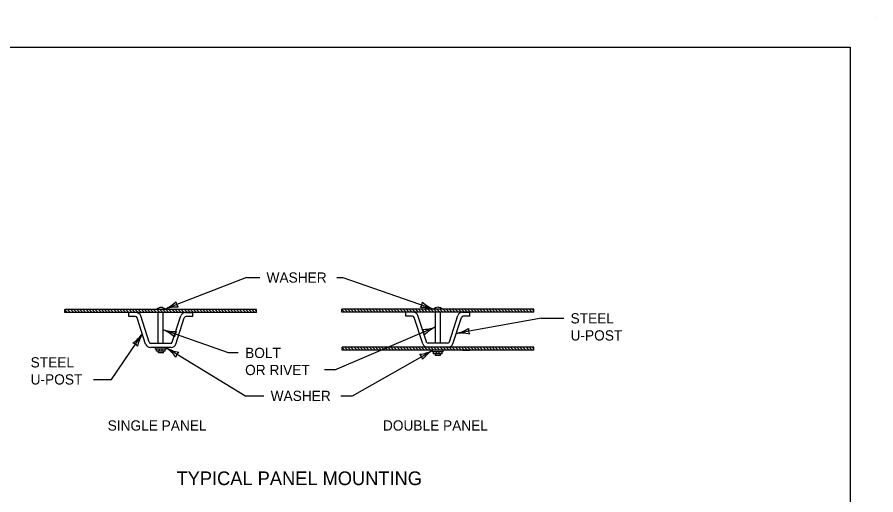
# Model space of a CAD drawing. Extents: x 49991.4 to 50021, y 49987.6 to 50011.4.
# Drawn here: x 50011.87 to 50016.9, y 49996.38 to 49999.18 of the extents above; entities that cross this region are included whole.
import ezdxf

# ---------------------------------------------------------------- set-up
doc = ezdxf.new("R2010")
doc.units = 0
for name, color, linetype in [('Level 1', 7, 'Continuous'), ('Level 2', 7, 'Continuous'), ('Level 3', 7, 'Continuous')]:
    doc.layers.add(name, color=color, linetype=linetype)

msp = doc.modelspace()

# ---------------------------------------------------------------- linework, layer by layer
at = {"layer": 'Level 1'}
for p, q in [((50016.9001, 49999.1756), (50016.9001, 49999.1756)), ((50012.1473, 49997.4466), (50012.1473, 49997.4642)), ((50013.2714, 49997.4642), (50012.1473, 49997.4642)), ((50012.1634, 49997.4466), (50012.1473, 49997.4626)), ((50012.1814, 49997.4466), (50012.1637, 49997.4642)), ((50012.1994, 49997.4466), (50012.1817, 49997.4642)), ((50012.2174, 49997.4466), (50012.1997, 49997.4642)), ((50012.2354, 49997.4466), (50012.2177, 49997.4642)), ((50012.2534, 49997.4466), (50012.2357, 49997.4642)), ((50012.2714, 49997.4466), (50012.2537, 49997.4642)), ((50012.2894, 49997.4466), (50012.2717, 49997.4642)), ((50012.3074, 49997.4466), (50012.2897, 49997.4642)), ((50012.3254, 49997.4466), (50012.3077, 49997.4642)), ((50012.3434, 49997.4466), (50012.3257, 49997.4642)), ((50012.3614, 49997.4466), (50012.3437, 49997.4642)), ((50012.3794, 49997.4466), (50012.3617, 49997.4642)), ((50012.3974, 49997.4466), (50012.3797, 49997.4642)), ((50012.4154, 49997.4466), (50012.3977, 49997.4642)), ((50012.4334, 49997.4466), (50012.4157, 49997.4642)), ((50012.4514, 49997.4466), (50012.4337, 49997.4642)), ((50012.4694, 49997.4466), (50012.4517, 49997.4642)), ((50012.4874, 49997.4466), (50012.4697, 49997.4642)), ((50012.5054, 49997.4466), (50012.4877, 49997.4642)), ((50012.5234, 49997.4466), (50012.5057, 49997.4642)), ((50012.5414, 49997.4466), (50012.5237, 49997.4642)), ((50012.5594, 49997.4466), (50012.5417, 49997.4642)), ((50012.5774, 49997.4466), (50012.5597, 49997.4642)), ((50012.5954, 49997.4466), (50012.5777, 49997.4642)), ((50012.6134, 49997.4466), (50012.5957, 49997.4642)), ((50012.6314, 49997.4466), (50012.6137, 49997.4642)), ((50012.6494, 49997.4466), (50012.6317, 49997.4642)), ((50012.6674, 49997.4466), (50012.6497, 49997.4642)), ((50012.6854, 49997.4466), (50012.6677, 49997.4642)), ((50012.7034, 49997.4466), (50012.6857, 49997.4642)), ((50012.7214, 49997.4466), (50012.7037, 49997.4642)), ((50012.7394, 49997.4466), (50012.7217, 49997.4642)), ((50012.7574, 49997.4466), (50012.7397, 49997.4642)), ((50012.7754, 49997.4466), (50012.7577, 49997.4642)), ((50012.7934, 49997.4466), (50012.7757, 49997.4642)), ((50012.8114, 49997.4466), (50012.7937, 49997.4642)), ((50012.8294, 49997.4466), (50012.8117, 49997.4642)), ((50012.8474, 49997.4466), (50012.8297, 49997.4642)), ((50012.8654, 49997.4466), (50012.8477, 49997.4642)), ((50012.8834, 49997.4466), (50012.8657, 49997.4642)), ((50012.9014, 49997.4466), (50012.8837, 49997.4642)), ((50012.9194, 49997.4466), (50012.9017, 49997.4642)), ((50012.9374, 49997.4466), (50012.9197, 49997.4642)), ((50012.9554, 49997.4466), (50012.9377, 49997.4642)), ((50012.9734, 49997.4466), (50012.9557, 49997.4642)), ((50012.9914, 49997.4466), (50012.9737, 49997.4642)), ((50013.0094, 49997.4466), (50012.9917, 49997.4642)), ((50013.0274, 49997.4466), (50013.0097, 49997.4642)), ((50013.0454, 49997.4466), (50013.0277, 49997.4642)), ((50013.0634, 49997.4466), (50013.0457, 49997.4642)), ((50013.0814, 49997.4466), (50013.0637, 49997.4642)), ((50013.0994, 49997.4466), (50013.0817, 49997.4642)), ((50013.1174, 49997.4466), (50013.0997, 49997.4642)), ((50013.1354, 49997.4466), (50013.1177, 49997.4642)), ((50013.1534, 49997.4466), (50013.1357, 49997.4642)), ((50013.1714, 49997.4466), (50013.1537, 49997.4642)), ((50013.1894, 49997.4466), (50013.1717, 49997.4642)), ((50013.2074, 49997.4466), (50013.1897, 49997.4642)), ((50013.2254, 49997.4466), (50013.2077, 49997.4642)), ((50013.2434, 49997.4466), (50013.2257, 49997.4642)), ((50013.2614, 49997.4466), (50013.2437, 49997.4642)), ((50013.2714, 49997.4546), (50013.2617, 49997.4642)), ((50013.2714, 49997.4466), (50013.2714, 49997.4642)), ((50013.7714, 49997.4482), (50013.7714, 49997.4658)), ((50014.8955, 49997.4658), (50013.7714, 49997.4658)), ((50013.7875, 49997.4482), (50013.7714, 49997.4642)), ((50014.8955, 49997.4482), (50013.7714, 49997.4482)), ((50013.8055, 49997.4482), (50013.7878, 49997.4658)), ((50013.8235, 49997.4482), (50013.8058, 49997.4658)), ((50013.8415, 49997.4482), (50013.8238, 49997.4658)), ((50013.8595, 49997.4482), (50013.8418, 49997.4658)), ((50013.8775, 49997.4482), (50013.8598, 49997.4658)), ((50013.8955, 49997.4482), (50013.8778, 49997.4658)), ((50013.9135, 49997.4482), (50013.8958, 49997.4658)), ((50013.9315, 49997.4482), (50013.9138, 49997.4658)), ((50013.9495, 49997.4482), (50013.9318, 49997.4658)), ((50013.9675, 49997.4482), (50013.9498, 49997.4658)), ((50013.9855, 49997.4482), (50013.9678, 49997.4658)), ((50014.0035, 49997.4482), (50013.9858, 49997.4658)), ((50014.0215, 49997.4482), (50014.0038, 49997.4658)), ((50014.0395, 49997.4482), (50014.0218, 49997.4658)), ((50014.0575, 49997.4482), (50014.0398, 49997.4658)), ((50014.0755, 49997.4482), (50014.0578, 49997.4658)), ((50014.0935, 49997.4482), (50014.0758, 49997.4658)), ((50014.1115, 49997.4482), (50014.0938, 49997.4658)), ((50014.1295, 49997.4482), (50014.1118, 49997.4658)), ((50014.1475, 49997.4482), (50014.1298, 49997.4658)), ((50014.1459, 49997.4247), (50014.1459, 49997.4482)), ((50014.1886, 49997.4482), (50014.1459, 49997.4482)), ((50014.1655, 49997.4482), (50014.1478, 49997.4658)), ((50014.1835, 49997.4482), (50014.1658, 49997.4658)), ((50014.2015, 49997.4482), (50014.1838, 49997.4658)), ((50014.2195, 49997.4482), (50014.2018, 49997.4658)), ((50014.2375, 49997.4482), (50014.2198, 49997.4658)), ((50014.2555, 49997.4482), (50014.2378, 49997.4658)), ((50014.2735, 49997.4482), (50014.2558, 49997.4658)), ((50014.2915, 49997.4482), (50014.2738, 49997.4658)), ((50014.3095, 49997.4482), (50014.2918, 49997.4658)), ((50014.3275, 49997.4482), (50014.3098, 49997.4658)), ((50014.3189, 49997.2665), (50014.3189, 49997.4482)), ((50014.3455, 49997.4482), (50014.3278, 49997.4658)), ((50014.3635, 49997.4482), (50014.3458, 49997.4658)), ((50014.3481, 49997.2665), (50014.3481, 49997.4482)), ((50014.3815, 49997.4482), (50014.3638, 49997.4658)), ((50014.3995, 49997.4482), (50014.3818, 49997.4658)), ((50014.4175, 49997.4482), (50014.3998, 49997.4658)), ((50014.4355, 49997.4482), (50014.4178, 49997.4658)), ((50014.4535, 49997.4482), (50014.4358, 49997.4658)), ((50014.4715, 49997.4482), (50014.4538, 49997.4658)), ((50014.4895, 49997.4482), (50014.4718, 49997.4658)), ((50014.4783, 49997.4482), (50014.521, 49997.4482)), ((50014.5075, 49997.4482), (50014.4898, 49997.4658)), ((50014.5255, 49997.4482), (50014.5078, 49997.4658)), ((50014.521, 49997.4247), (50014.521, 49997.4482)), ((50014.5435, 49997.4482), (50014.5258, 49997.4658)), ((50014.5615, 49997.4482), (50014.5438, 49997.4658)), ((50014.5795, 49997.4482), (50014.5618, 49997.4658)), ((50014.5975, 49997.4482), (50014.5798, 49997.4658)), ((50014.6155, 49997.4482), (50014.5978, 49997.4658)), ((50014.6335, 49997.4482), (50014.6158, 49997.4658)), ((50014.6515, 49997.4482), (50014.6338, 49997.4658)), ((50014.6695, 49997.4482), (50014.6518, 49997.4658)), ((50014.6875, 49997.4482), (50014.6698, 49997.4658)), ((50014.7055, 49997.4482), (50014.6878, 49997.4658)), ((50014.7235, 49997.4482), (50014.7058, 49997.4658)), ((50014.7415, 49997.4482), (50014.7238, 49997.4658)), ((50014.7595, 49997.4482), (50014.7418, 49997.4658)), ((50014.7775, 49997.4482), (50014.7598, 49997.4658)), ((50014.7955, 49997.4482), (50014.7778, 49997.4658)), ((50014.8135, 49997.4482), (50014.7958, 49997.4658)), ((50014.8315, 49997.4482), (50014.8138, 49997.4658)), ((50014.8495, 49997.4482), (50014.8318, 49997.4658)), ((50014.8675, 49997.4482), (50014.8498, 49997.4658)), ((50014.8855, 49997.4482), (50014.8678, 49997.4658)), ((50014.8955, 49997.4562), (50014.8858, 49997.4658)), ((50014.8955, 49997.4482), (50014.8955, 49997.4658)), ((50013.2714, 49997.4466), (50012.1473, 49997.4466)), ((50012.5218, 49997.4231), (50012.5218, 49997.4466)), ((50012.5645, 49997.4466), (50012.5218, 49997.4466)), ((50012.5601, 49997.4231), (50012.5218, 49997.4231)), ((50012.6208, 49997.2617), (50012.5713, 49997.415)), ((50012.6418, 49997.2731), (50012.5923, 49997.4263)), ((50012.6948, 49997.2649), (50012.6948, 49997.4466)), ((50012.724, 49997.2649), (50012.724, 49997.4466)), ((50012.7769, 49997.273), (50012.8263, 49997.4263)), ((50012.7979, 49997.2617), (50012.8474, 49997.415)), ((50012.8542, 49997.4466), (50012.8969, 49997.4466)), ((50012.8969, 49997.4231), (50012.8585, 49997.4231)), ((50012.8969, 49997.4231), (50012.8969, 49997.4466)), ((50014.1842, 49997.4247), (50014.1459, 49997.4247)), ((50014.2449, 49997.2633), (50014.1954, 49997.4166)), ((50014.2659, 49997.2747), (50014.2164, 49997.4279)), ((50014.401, 49997.2746), (50014.4504, 49997.4279)), ((50014.422, 49997.2633), (50014.4715, 49997.4166)), ((50014.521, 49997.4247), (50014.4826, 49997.4247)), ((50012.7657, 49997.2649), (50012.6529, 49997.2649)), ((50014.3898, 49997.2665), (50014.277, 49997.2665)), ((50012.7701, 49997.2414), (50012.6486, 49997.2414)), ((50012.6787, 49997.2311), (50012.6787, 49997.2414)), ((50012.7413, 49997.2311), (50012.6787, 49997.2311)), ((50012.6846, 49997.2201), (50012.6846, 49997.2311)), ((50012.7354, 49997.2201), (50012.6846, 49997.2201)), ((50012.6955, 49997.2099), (50012.6955, 49997.2201)), ((50012.7247, 49997.2099), (50012.6955, 49997.2099)), ((50012.7015, 49997.2201), (50012.7015, 49997.2311)), ((50012.7186, 49997.2201), (50012.7186, 49997.2311)), ((50012.7247, 49997.2099), (50012.7247, 49997.2201)), ((50012.7354, 49997.2201), (50012.7354, 49997.2311)), ((50012.7413, 49997.2311), (50012.7413, 49997.2414)), ((50013.7717, 49997.2253), (50013.7717, 49997.2429)), ((50014.8958, 49997.2429), (50013.7717, 49997.2429)), ((50013.7878, 49997.2253), (50013.7717, 49997.2413)), ((50014.8958, 49997.2253), (50013.7717, 49997.2253)), ((50013.8058, 49997.2253), (50013.7881, 49997.2429)), ((50013.8238, 49997.2253), (50013.8061, 49997.2429)), ((50013.8418, 49997.2253), (50013.8241, 49997.2429)), ((50013.8598, 49997.2253), (50013.8421, 49997.2429)), ((50013.8778, 49997.2253), (50013.8601, 49997.2429)), ((50013.8958, 49997.2253), (50013.8781, 49997.2429)), ((50013.9138, 49997.2253), (50013.8961, 49997.2429)), ((50013.9318, 49997.2253), (50013.9141, 49997.2429)), ((50013.9498, 49997.2253), (50013.9321, 49997.2429)), ((50013.9678, 49997.2253), (50013.9501, 49997.2429)), ((50013.9858, 49997.2253), (50013.9681, 49997.2429)), ((50014.0038, 49997.2253), (50013.9861, 49997.2429)), ((50014.0218, 49997.2253), (50014.0041, 49997.2429)), ((50014.0398, 49997.2253), (50014.0221, 49997.2429)), ((50014.0578, 49997.2253), (50014.0401, 49997.2429)), ((50014.0758, 49997.2253), (50014.0581, 49997.2429)), ((50014.0938, 49997.2253), (50014.0761, 49997.2429)), ((50014.1118, 49997.2253), (50014.0941, 49997.2429)), ((50014.1298, 49997.2253), (50014.1121, 49997.2429)), ((50014.1478, 49997.2253), (50014.1301, 49997.2429)), ((50014.1889, 49997.2253), (50014.1462, 49997.2253)), ((50014.1658, 49997.2253), (50014.1481, 49997.2429)), ((50014.1838, 49997.2253), (50014.1661, 49997.2429)), ((50014.2018, 49997.2253), (50014.1841, 49997.2429)), ((50014.2198, 49997.2253), (50014.2021, 49997.2429)), ((50014.2378, 49997.2253), (50014.2201, 49997.2429)), ((50014.2558, 49997.2253), (50014.2381, 49997.2429)), ((50014.2738, 49997.2253), (50014.2561, 49997.2429)), ((50014.3942, 49997.243), (50014.2727, 49997.243)), ((50014.2918, 49997.2253), (50014.2741, 49997.2429)), ((50014.3098, 49997.2253), (50014.2921, 49997.2429)), ((50014.3021, 49997.2153), (50014.3021, 49997.2253)), ((50014.3647, 49997.2153), (50014.3021, 49997.2153)), ((50014.308, 49997.2043), (50014.308, 49997.2153)), ((50014.3588, 49997.2043), (50014.308, 49997.2043)), ((50014.3278, 49997.2253), (50014.3101, 49997.2429)), ((50014.3189, 49997.1941), (50014.3189, 49997.2043)), ((50014.3249, 49997.2043), (50014.3249, 49997.2153)), ((50014.3458, 49997.2253), (50014.3281, 49997.2429)), ((50014.342, 49997.2043), (50014.342, 49997.2153)), ((50014.3638, 49997.2253), (50014.3461, 49997.2429)), ((50014.3481, 49997.1941), (50014.3481, 49997.2043)), ((50014.3588, 49997.2043), (50014.3588, 49997.2153)), ((50014.3818, 49997.2253), (50014.3641, 49997.2429)), ((50014.3647, 49997.2153), (50014.3647, 49997.2253)), ((50014.3998, 49997.2253), (50014.3821, 49997.2429)), ((50014.4178, 49997.2253), (50014.4001, 49997.2429)), ((50014.4358, 49997.2253), (50014.4181, 49997.2429)), ((50014.4538, 49997.2253), (50014.4361, 49997.2429)), ((50014.4718, 49997.2253), (50014.4541, 49997.2429)), ((50014.4898, 49997.2253), (50014.4721, 49997.2429)), ((50014.4786, 49997.2253), (50014.5213, 49997.2253)), ((50014.5078, 49997.2253), (50014.4901, 49997.2429)), ((50014.5258, 49997.2253), (50014.5081, 49997.2429)), ((50014.5438, 49997.2253), (50014.5261, 49997.2429)), ((50014.5618, 49997.2253), (50014.5441, 49997.2429)), ((50014.5798, 49997.2253), (50014.5621, 49997.2429)), ((50014.5978, 49997.2253), (50014.5801, 49997.2429)), ((50014.6158, 49997.2253), (50014.5981, 49997.2429)), ((50014.6338, 49997.2253), (50014.6161, 49997.2429)), ((50014.6518, 49997.2253), (50014.6341, 49997.2429)), ((50014.6698, 49997.2253), (50014.6521, 49997.2429)), ((50014.6878, 49997.2253), (50014.6701, 49997.2429)), ((50014.7058, 49997.2253), (50014.6881, 49997.2429)), ((50014.7238, 49997.2253), (50014.7061, 49997.2429)), ((50014.7418, 49997.2253), (50014.7241, 49997.2429)), ((50014.7598, 49997.2253), (50014.7421, 49997.2429)), ((50014.7778, 49997.2253), (50014.7601, 49997.2429)), ((50014.7958, 49997.2253), (50014.7781, 49997.2429)), ((50014.8138, 49997.2253), (50014.7961, 49997.2429)), ((50014.8318, 49997.2253), (50014.8141, 49997.2429)), ((50014.8498, 49997.2253), (50014.8321, 49997.2429)), ((50014.8678, 49997.2253), (50014.8501, 49997.2429)), ((50014.8858, 49997.2253), (50014.8681, 49997.2429)), ((50014.8958, 49997.2333), (50014.8861, 49997.2429)), ((50014.8958, 49997.2253), (50014.8958, 49997.2429)), ((50014.3481, 49997.1941), (50014.3189, 49997.1941))]:
    msp.add_line(p, q, dxfattribs=at)
msp.add_lwpolyline([(49999.3835, 49998.9992), (50016.7501, 49998.9992), (50016.7501, 49987.7988), (49999.3835, 49987.7988)], close=True, dxfattribs=at)
for centre, radius, start, end in [((50012.7104, 49997.4409), 0.0347, 42.1586, 137.8397), ((50014.1887, 49997.4189), 0.0293, 17.888, 90), ((50014.3345, 49997.4425), 0.0347, 42.1586, 137.8397), ((50014.4783, 49997.4189), 0.0293, 90, 162.1111), ((50012.5602, 49997.4113), 0.0117, 17.8891, 90), ((50012.5646, 49997.4173), 0.0293, 17.888, 90), ((50012.8542, 49997.4173), 0.0293, 90, 162.1111), ((50012.8585, 49997.4113), 0.0117, 90, 162.1109), ((50014.1843, 49997.4129), 0.0117, 17.8891, 90), ((50014.4826, 49997.4129), 0.0117, 90, 162.1109), ((50012.6487, 49997.2707), 0.0293, 197.8891, 270), ((50012.6529, 49997.2767), 0.0117, 197.8889, 270), ((50012.7657, 49997.2767), 0.0117, 270, 342.1111), ((50012.7701, 49997.2707), 0.0293, 270, 342.1109), ((50014.2728, 49997.2723), 0.0293, 197.8891, 270), ((50014.277, 49997.2783), 0.0117, 197.8889, 270), ((50014.3898, 49997.2783), 0.0117, 270, 342.1111), ((50014.3942, 49997.2723), 0.0293, 270, 342.1109)]:
    msp.add_arc(centre, radius, start, end, dxfattribs=at)
at = {"layer": 'Level 3'}
for p, q in [((50013.2117, 49997.6512), (50012.7338, 49997.4666)), ((50013.2117, 49997.6512), (50013.2895, 49997.6512)), ((50013.7409, 49997.6512), (50013.776, 49997.6512)), ((50013.776, 49997.6512), (50014.3089, 49997.4659)), ((50014.941, 49997.4123), (50014.4414, 49997.3232)), ((50014.941, 49997.4123), (50015.0712, 49997.4123)), ((50013.7293, 49997.1098), (50014.3189, 49997.3616)), ((50012.4205, 49997.0546), (50012.6017, 49997.3209)), ((50013.1067, 49997.2098), (50012.724, 49997.3447)), ((50013.202, 49996.9583), (50012.7413, 49997.2393)), ((50013.1639, 49997.2098), (50013.1067, 49997.2098)), ((50013.8325, 49996.9583), (50014.3021, 49997.2246)), ((50013.7293, 49997.1098), (50013.669, 49997.1098)), ((50012.3148, 49997.0546), (50012.4205, 49997.0546)), ((50013.202, 49996.9583), (50013.3134, 49996.9583)), ((50013.7648, 49996.9583), (50013.8325, 49996.9583))]:
    msp.add_line(p, q, dxfattribs=at)
for centre, radius, start, end in [((50012.6392, 49997.6795), 0.233, 293.9466, 313.1964), ((50012.8534, 49997.5128), 0.0548, 183.2581, 218.9804), ((50014.1878, 49997.508), 0.0548, 322.9653, 358.6877), ((50014.3905, 49997.6727), 0.2223, 228.2825, 248.466), ((50012.8053, 49997.2561), 0.2223, 88.5753, 108.7588), ((50014.2433, 49997.2423), 0.233, 73.6538, 92.9036), ((50014.2401, 49997.5695), 0.2223, 270.5813, 290.7648), ((50014.201, 49997.3113), 0.0548, 5.2641, 40.9864), ((50014.4209, 49997.1521), 0.233, 115.9526, 135.2024), ((50014.3879, 49997.55), 0.233, 283.2775, 302.5273), ((50014.5675, 49997.3465), 0.0548, 172.589, 208.3113), ((50012.4232, 49997.4534), 0.2223, 303.2183, 323.4019), ((50012.8006, 49997.1994), 0.233, 148.5896, 167.8395), ((50012.6416, 49997.1382), 0.2223, 48.0448, 68.2283), ((50012.7905, 49997.568), 0.233, 253.4161, 272.6659), ((50012.845, 49997.3021), 0.0548, 142.7276, 178.4499), ((50014.4727, 49997.1031), 0.2223, 77.9062, 98.0897), ((50012.5296, 49997.2149), 0.0548, 37.9012, 73.6235), ((50012.6178, 49997.0545), 0.2223, 36.0723, 56.2558), ((50012.8527, 49997.444), 0.233, 241.4436, 260.6934), ((50012.8508, 49997.1726), 0.0548, 130.7551, 166.4774), ((50014.2005, 49997.4224), 0.2223, 277.0137, 297.1972), ((50014.1906, 49997.1614), 0.0548, 11.6965, 47.4189), ((50014.4269, 49997.0279), 0.233, 122.385, 141.6348)]:
    msp.add_arc(centre, radius, start, end, dxfattribs=at)

# ---------------------------------------------------------------- texts
at = {"layer": 'Level 2'}
for s, height, p in [('WASHER', 0.06, (50013.3295, 49997.6212)), ('STEEL', 0.06, (50015.1112, 49997.3823)), ('U-POST', 0.06, (50015.1112, 49997.2823)), ('BOLT', 0.06, (50013.2039, 49997.1798)), ('STEEL', 0.06, (50011.9469, 49997.1246)), ('OR RIVET', 0.06, (50013.2039, 49997.0798)), ('U-POST', 0.06, (50011.9469, 49997.0246)), ('WASHER', 0.06, (50013.3534, 49996.9283)), ('SINGLE PANEL', 0.06, (50012.3984, 49996.7548)), ('DOUBLE PANEL', 0.06, (50014.0116, 49996.7548)), ('TYPICAL PANEL MOUNTING', 0.08, (50012.8018, 49996.4356))]:
    msp.add_text(s, height=height, dxfattribs=at).set_placement(p)

doc.saveas('drawing.dxf')
